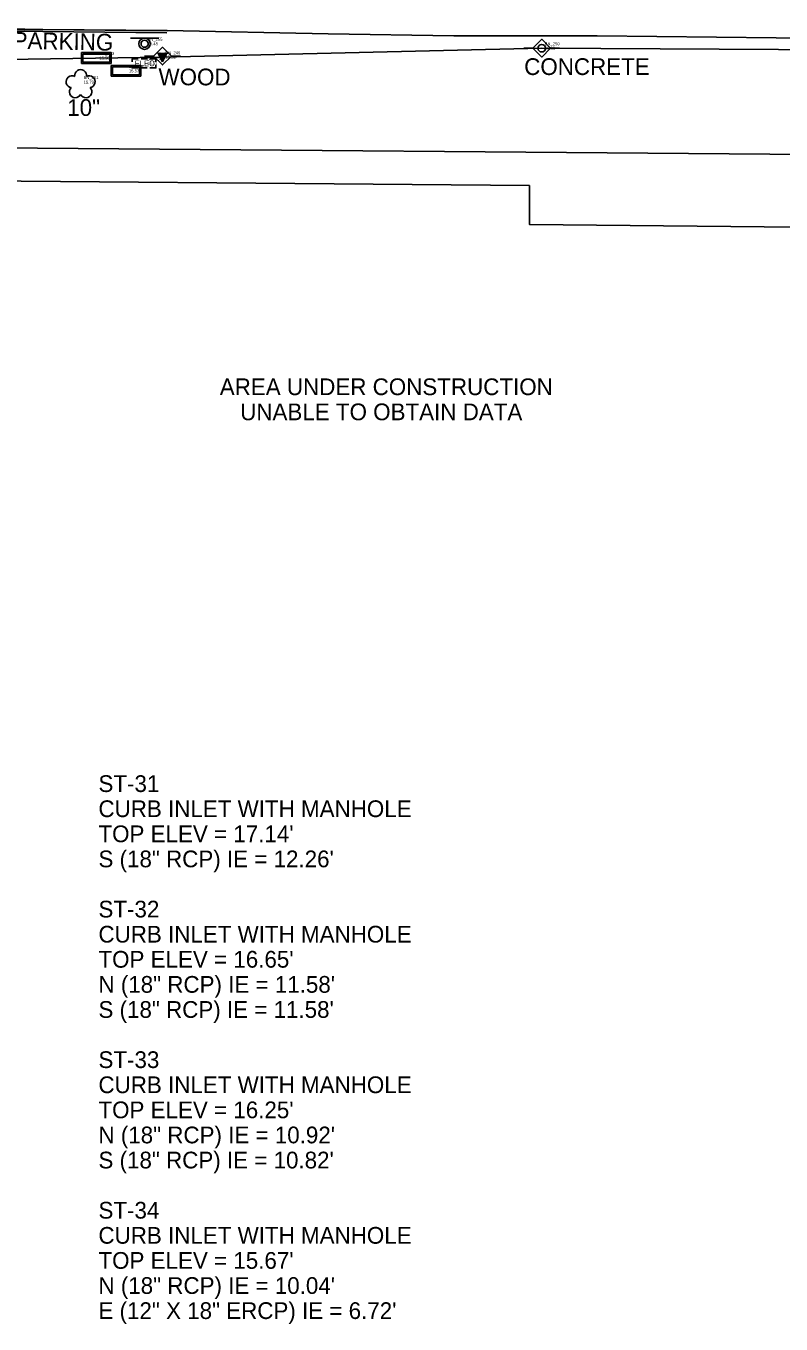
# Model space of a CAD drawing. Extents: x 509744 to 512285, y 1314862 to 1316822.
# Drawn here: x 511339 to 511465.4, y 1315382.8 to 1315600.1 of the extents above; entities that cross this region are included whole.
import ezdxf

# ---------------------------------------------------------------- set-up
doc = ezdxf.new("R2010")
doc.units = 0
for name, color, linetype in [('Building_ep', 7, 'Continuous'), ('CGBack_ep', 7, 'Continuous'), ('CGFace_ep', 7, 'Continuous'), ('ElecAer_ep', 7, 'Continuous'), ('JunctBox_ep', 7, 'Continuous'), ('MeterElec_ep', 7, 'Continuous'), ('NonPlottingEle_dp', 7, 'Continuous'), ('PavtAsphalt_ep', 7, 'Continuous'), ('PoleElecT_ep', 7, 'Continuous'), ('PoleShared_ep', 7, 'Continuous'), ('RWLine_ep', 7, 'Continuous'), ('SignSingle_ep', 7, 'Continuous'), ('TextElevLabel', 7, 'Continuous'), ('TextPtLabel', 7, 'Continuous'), ('TextTopoLabel_ep', 7, 'Continuous'), ('TextUtilLabel_ep', 7, 'Continuous'), ('Tree_ep', 7, 'Continuous')]:
    doc.layers.add(name, color=color, linetype=linetype)

msp = doc.modelspace()

# ---------------------------------------------------------------- linework, layer by layer
at = {"layer": 'Building_ep'}
msp.add_lwpolyline([(511286.15, 1315576.44), (511305.48, 1315576.3), (511305.48, 1315574.36), (511423.31, 1315573.35), (511423.3, 1315566.86), (511614.13, 1315564.95), (511614.09, 1315555.08)], dxfattribs=at)
at = {"layer": 'CGBack_ep'}
msp.add_line((511341.83, 1315599.13), (511362.63, 1315598.94), dxfattribs=at)
msp.add_lwpolyline([(511286.15, 1315599.52), (511311.83, 1315599.57), (511335.83, 1315599.22), (511338.83, 1315599.18), (511341.83, 1315599.13)], dxfattribs=at)
at = {"layer": 'CGFace_ep'}
msp.add_line((511362.64, 1315599.27), (511341.83, 1315599.47), dxfattribs=at)
msp.add_lwpolyline([(511286.15, 1315599.98), (511311.83, 1315599.91), (511335.83, 1315599.56), (511338.83, 1315599.5), (511341.83, 1315599.47)], dxfattribs=at)
at = {"layer": 'ElecAer_ep'}
msp.add_lwpolyline([(511279.43, 1315593.6), (511361.88, 1315594.83), (511425.37, 1315596.34), (511633.33, 1315595.17), (511730.23, 1315594.11), (511729.51, 1315528.94)], dxfattribs=at)
at = {"layer": 'JunctBox_ep'}
for p, q in [((511348.3, 1315595.6), (511353.3, 1315595.6)), ((511348.3, 1315593.78), (511348.3, 1315595.6)), ((511348.55, 1315595.35), (511353.06, 1315595.35)), ((511348.55, 1315594.03), (511348.55, 1315595.35)), ((511353.06, 1315594.03), (511348.55, 1315594.03)), ((511353.06, 1315595.35), (511353.06, 1315594.03)), ((511353.3, 1315595.6), (511353.3, 1315593.78)), ((511353.3, 1315593.78), (511348.3, 1315593.78)), ((511353.27, 1315593.46), (511358.27, 1315593.46)), ((511353.27, 1315591.64), (511353.27, 1315593.46)), ((511353.52, 1315593.21), (511358.02, 1315593.21)), ((511353.52, 1315591.89), (511353.52, 1315593.21)), ((511358.02, 1315591.89), (511353.52, 1315591.89)), ((511358.02, 1315593.21), (511358.02, 1315591.89)), ((511358.27, 1315593.46), (511358.27, 1315591.64)), ((511358.27, 1315591.64), (511353.27, 1315591.64))]:
    msp.add_line(p, q, dxfattribs=at)
at = {"layer": 'MeterElec_ep'}
for points in [[(511356.79, 1315594.05), (511356.79, 1315594.56), (511357.79, 1315594.56)], [(511358.29, 1315594.56), (511359.29, 1315594.56)], [(511359.79, 1315594.56), (511360.79, 1315594.56), (511360.79, 1315594.05)], [(511357.79, 1315593.05), (511356.79, 1315593.05), (511356.79, 1315593.55)], [(511359.29, 1315593.05), (511358.29, 1315593.05)], [(511360.79, 1315593.55), (511360.79, 1315593.05), (511359.79, 1315593.05)]]:
    msp.add_lwpolyline(points, dxfattribs=at)
at = {"layer": 'PavtAsphalt_ep'}
msp.add_line((511341.83, 1315599.5), (511362.64, 1315599.31), dxfattribs=at)
for points in [[(511286.15, 1315600.07), (511311.83, 1315599.93), (511335.83, 1315599.59), (511338.83, 1315599.54), (511341.83, 1315599.5)], [(511362.64, 1315599.31), (511389.63, 1315598.77), (511410.63, 1315598.39), (511434.63, 1315598.41), (511464.63, 1315598.07), (511497.63, 1315597.91), (511500.63, 1315597.87), (511534.89, 1315597.93), (511567.89, 1315596.76), (511594.89, 1315597.79), (511603.89, 1315597.78), (511633.89, 1315596.77)]]:
    msp.add_lwpolyline(points, dxfattribs=at)
at = {"layer": 'PoleElecT_ep'}
for p, q in [((511358.89, 1315595.03), (511360.39, 1315595.03)), ((511361.88, 1315594.08), (511361.13, 1315595.57)), ((511361.88, 1315594.08), (511361.33, 1315595.57)), ((511361.88, 1315594.08), (511361.51, 1315595.57)), ((511361.88, 1315594.08), (511361.7, 1315595.57)), ((511361.88, 1315594.08), (511362.63, 1315595.57)), ((511361.88, 1315594.08), (511362.25, 1315595.57)), ((511361.88, 1315594.08), (511362.42, 1315595.57)), ((511361.88, 1315594.08), (511362.06, 1315595.57)), ((511361.88, 1315594.08), (511361.88, 1315595.57)), ((511364.87, 1315595.03), (511363.37, 1315595.03))]:
    msp.add_line(p, q, dxfattribs=at)
msp.add_lwpolyline([(511360.39, 1315595.03), (511361.88, 1315596.51), (511363.37, 1315595.03), (511361.88, 1315593.54), (511360.39, 1315595.03)], dxfattribs=at)
at = {"layer": 'PoleShared_ep'}
for p, q in [((511422.38, 1315596.34), (511423.88, 1315596.34)), ((511428.36, 1315596.34), (511426.86, 1315596.34))]:
    msp.add_line(p, q, dxfattribs=at)
msp.add_lwpolyline([(511423.88, 1315596.34), (511425.37, 1315597.83), (511426.86, 1315596.34), (511425.37, 1315594.85), (511423.88, 1315596.34)], dxfattribs=at)
msp.add_circle((511425.37, 1315596.34), 0.625, dxfattribs=at)
at = {"layer": 'RWLine_ep'}
msp.add_line((511261.23, 1315580.31), (512253.43, 1315571.92), dxfattribs=at)
at = {"layer": 'SignSingle_ep'}
msp.add_line((511356.51, 1315598.04), (511361.26, 1315598.04), dxfattribs=at)
for radius in [0.95, 0.594]:
    msp.add_circle((511358.88, 1315597.09), radius, dxfattribs=at)
at = {"layer": 'Tree_ep'}
for centre, start, end in [((511348.17, 1315591.76), 352.1546, 187.8454), ((511346.75, 1315590.73), 64.1546, 259.8454), ((511347.29, 1315589.05), 136.1546, 331.8454), ((511349.05, 1315589.05), 208.1546, 43.8454), ((511349.6, 1315590.73), 280.1546, 115.8454)]:
    msp.add_arc(centre, 1, start, end, dxfattribs=at)

# ---------------------------------------------------------------- texts
at = {"layer": 'MeterElec_ep'}
msp.add_text('ELEC', height=0.95, dxfattribs=at).set_placement((511357.24, 1315593.33))
at = {"layer": 'NonPlottingEle_dp'}
for s, p in [('ST-31', (511351.16, 1315471.86)), ('CURB INLET WITH MANHOLE', (511351.16, 1315467.66)), ("TOP ELEV = 17.14'", (511351.16, 1315463.46)), ('S (18" RCP) IE = 12.26\'', (511351.16, 1315459.26)), ('ST-32', (511351.16, 1315450.86)), ('CURB INLET WITH MANHOLE', (511351.16, 1315446.66)), ("TOP ELEV = 16.65'", (511351.16, 1315442.46)), ('N (18" RCP) IE = 11.58\'', (511351.16, 1315438.26)), ('S (18" RCP) IE = 11.58\'', (511351.16, 1315434.06)), ('ST-33', (511351.16, 1315425.66)), ('CURB INLET WITH MANHOLE', (511351.16, 1315421.46)), ("TOP ELEV = 16.25'", (511351.16, 1315417.26)), ('N (18" RCP) IE = 10.92\'', (511351.16, 1315413.06)), ('S (18" RCP) IE = 10.82\'', (511351.16, 1315408.86)), ('ST-34', (511351.16, 1315400.46)), ('CURB INLET WITH MANHOLE', (511351.16, 1315396.26)), ("TOP ELEV = 15.67'", (511351.16, 1315392.06)), ('N (18" RCP) IE = 10.04\'', (511351.16, 1315387.86)), ('E (12" X 18" ERCP) IE = 6.72\'', (511351.16, 1315383.66))]:
    msp.add_text(s, height=2.8, dxfattribs=at).set_placement(p)
at = {"layer": 'TextElevLabel'}
for s, p in [('15.48', (511359.38, 1315596.84)), ('20.38', (511425.87, 1315596.09)), ('15.58', (511351.3, 1315594.44)), ('15.51', (511359.29, 1315593.56)), ('15.31', (511362.38, 1315594.58)), ('15.57', (511356.26, 1315592.3)), ('15.79', (511348.67, 1315590.42))]:
    msp.add_text(s, height=0.5, dxfattribs=at).set_placement(p)
at = {"layer": 'TextPtLabel'}
for s, p in [('BN_255', (511359.38, 1315597.59)), ('BN_250', (511425.87, 1315596.84)), ('BN_253', (511351.3, 1315595.19)), ('BN_254', (511359.29, 1315594.31)), ('BN_249', (511362.38, 1315595.33)), ('BN_252', (511356.26, 1315593.05)), ('BN_251', (511348.67, 1315591.17))]:
    msp.add_text(s, height=0.5, dxfattribs=at).set_placement(p)
at = {"layer": 'TextTopoLabel_ep'}
msp.add_text('NO PARKING', height=2.8, rotation=358.8088, dxfattribs=at).set_placement((511330.11, 1315596.41))
for s, p in [('CONCRETE', (511422.43, 1315591.86)), ('10"', (511345.93, 1315585.01)), ('AREA UNDER CONSTRUCTION', (511371.47, 1315538.28)), ('UNABLE TO OBTAIN DATA', (511374.89, 1315534.08))]:
    msp.add_text(s, height=2.8, dxfattribs=at).set_placement(p)
at = {"layer": 'TextUtilLabel_ep'}
msp.add_text('WOOD', height=2.8, rotation=359.854, dxfattribs=at).set_placement((511361.21, 1315590.15))

doc.saveas('drawing.dxf')
